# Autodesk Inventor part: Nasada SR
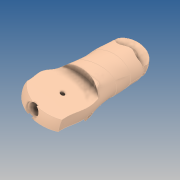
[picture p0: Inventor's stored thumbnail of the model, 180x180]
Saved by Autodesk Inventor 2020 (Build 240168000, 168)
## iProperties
Created: 2019-10
Part Number: Nasada SR
Material: GFRP
Document SubType Name: Modeling
Designer: yello
Density: 1.75 g/cm^3
Appearance: Default
Author: yello
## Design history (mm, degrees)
feature "Nasada SR"
workplane "Work Plane1"
sketch "Sketch1"
  geometry: L1 (-3.5, 0.006)-(-3.532, -19.994); L2 (-3.532, -19.994)-(3.468, -20.006); L3 (3.468, -20.006)-(3.5, -0.006); L4 (3.5, -0.006)-(3.548, 29.994); L5 (3.548, 29.994)-(-3.452, 30.006); L6 (-3.452, 30.006)-(-3.5, 0.006); L7 (0.048, 30)-(-0.032, -20); A1 r 3.5 centre (0, 0) between (-3.5, 0.006) and (3.5, -0.006); 1 further point
  constraints: 14 end point, 3 perpendicular, 2 midpoint, 2 point on circle, 2 point on line, 2 tangent, 1 centre point
  dimensions: "d0" = 7 diameter of A1; "d1" = 20 distance of L1.start L1.end; "d2" = 30 distance of L3.end L4.end
revolve "Revolution1" sketch "Sketch1" stored, may be unused: angle "d3" = 90 deg
workplane "Work Plane2"
sketch "Sketch2"
  geometry: C1 r 4.25 at (0, 0)
  constraints: 1 centre point
  dimensions: "d5" = 8.5 diameter of C1
extrude "Extrusion1" cut sketch "Sketch2" distance "d6" = 1.75; taper "d7" = 0 deg
workplane "Work Plane3"
sketch "Sketch3"
  geometry: L1 (-3.101, 29.402)-(-9.983, 30.68) reference; L2 (-18.43, -14.792)-(-11.548, -16.07) reference; L3 (-6.542, 30.041)-(-12.021, 0.546); L4 (-12.021, 0.546)-(-12.675, -2.975); C1 r 1.5 at (-12.021, 0.546); 3 further points
  constraints: 4 end point, 1 centre point, 1 coincident, 1 midpoint, 1 perpendicular
  dimensions: "d9" = 30 distance of L3.start L3.end; "d10" = 3 diameter of C1
revolve "Revolution2" sketch "Sketch3" stored, may be unused: angle "d11" = 90 deg
mirror "Mirror1"
workplane "Work Plane4"
sketch "Sketch5"
  geometry: L1 (28.5, -7)-(28.5, 0) reference; L2 (28.5, -3.5)-(24.75, -3.5); L3 (24.75, -3.5)-(16.5, -3.5); L4 (24.75, -2.5)-(16.5, -2.5); L5 (16.5, -4.5)-(24.75, -4.5); A1 r 1 centre (24.75, -3.5) between (24.75, -4.5) and (24.75, -2.5); A2 r 1 centre (16.5, -3.5) between (16.5, -2.5) and (16.5, -4.5); 2 further points
  constraints: 10 end point, 4 point on circle, 4 tangent, 2 centre point, 2 horizontal, 2 midpoint, 1 parallel
  dimensions: "d15" = 3.75 distance of L2.start L2.end; "d16" = 8.25 distance of L2.end L3.end; "d17" = 2 diameter of A2
extrude "Extrusion3" cut sketch "Sketch5" distance "d18" = 324; taper "d19" = 0 deg
sketch "Sketch6"
  geometry: C1 r 2 at (0, 0); C2 r 5 at (0, 0); 1 further point
  constraints: 2 centre point, 1 coincident
  dimensions: "d20" = 4 diameter of C1; "d21" = 10 diameter of C2
extrude "Extrusion4" cut sketch "Sketch6" distance "d22" = 8; taper "d23" = 0 deg
body "Solid1"
other parameters: "sa_0" = 4, "d4" = 48, "d8" = -0.5
